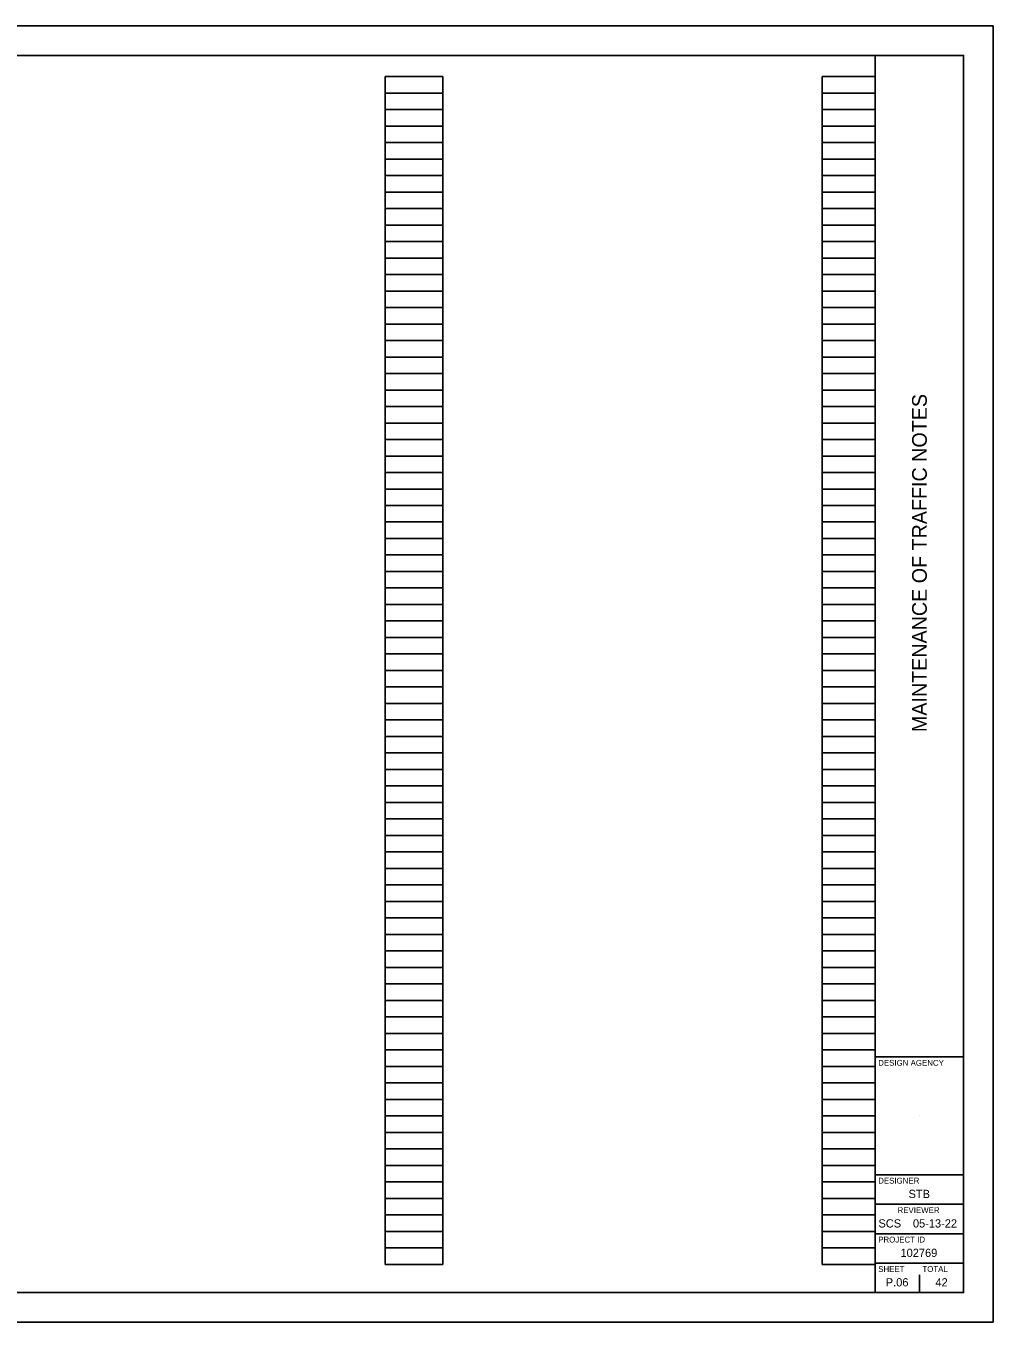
# Model space of a CAD drawing. Extents: x 0 to 34, y -1.2 to 22.
# Drawn here: x 17.58 to 34, y 0 to 22 of the extents above; entities that cross this region are included whole.
import ezdxf

# ---------------------------------------------------------------- set-up
doc = ezdxf.new("R2010")
doc.units = 0
for name, color, linetype in [('SH_Border', 7, 'Continuous'), ('SH_Cut_Line', 7, 'Continuous'), ('SH_Data', 7, 'Continuous')]:
    doc.layers.add(name, color=color, linetype=linetype)

msp = doc.modelspace()

# ---------------------------------------------------------------- linework, layer by layer
at = {"layer": 'SH_Border'}
for p, q in [((32, 0.5), (32, 21.5)), ((32, 4.5), (33.5, 4.5)), ((32, 2.5), (33.5, 2.5)), ((32, 2), (33.5, 2)), ((32, 1.5), (33.5, 1.5)), ((32, 1), (33.5, 1))]:
    msp.add_line(p, q, dxfattribs=at)
msp.add_lwpolyline([(1.5, 21.5), (33.5, 21.5), (33.5, 0.5), (1.5, 0.5)], close=True, dxfattribs=at)
at = {"layer": 'SH_Cut_Line'}
msp.add_lwpolyline([(0, 0), (34, 0), (34, 22), (0, 22)], close=True, dxfattribs=at)
at = {"layer": 'SH_Data'}
for p, q in [((23.68, 0.98), (23.68, 21.14)), ((23.68, 21.14), (24.66, 21.14)), ((24.66, 0.98), (24.66, 21.14)), ((31.1, 0.98), (31.1, 21.14)), ((31.1, 21.14), (32, 21.14)), ((32, 0.98), (32, 21.14)), ((23.68, 20.86), (24.66, 20.86)), ((31.1, 20.86), (32, 20.86)), ((23.68, 20.58), (24.66, 20.58)), ((31.1, 20.58), (32, 20.58)), ((23.68, 20.3), (24.66, 20.3)), ((31.1, 20.3), (32, 20.3)), ((23.68, 20.02), (24.66, 20.02)), ((31.1, 20.02), (32, 20.02)), ((23.68, 19.74), (24.66, 19.74)), ((31.1, 19.74), (32, 19.74)), ((23.68, 19.46), (24.66, 19.46)), ((31.1, 19.46), (32, 19.46)), ((23.68, 19.18), (24.66, 19.18)), ((31.1, 19.18), (32, 19.18)), ((23.68, 18.9), (24.66, 18.9)), ((31.1, 18.9), (32, 18.9)), ((23.68, 18.62), (24.66, 18.62)), ((31.1, 18.62), (32, 18.62)), ((23.68, 18.34), (24.66, 18.34)), ((31.1, 18.34), (32, 18.34)), ((23.68, 18.06), (24.66, 18.06)), ((31.1, 18.06), (32, 18.06)), ((23.68, 17.78), (24.66, 17.78)), ((31.1, 17.78), (32, 17.78)), ((23.68, 17.5), (24.66, 17.5)), ((31.1, 17.5), (32, 17.5)), ((23.68, 17.22), (24.66, 17.22)), ((31.1, 17.22), (32, 17.22)), ((23.68, 16.94), (24.66, 16.94)), ((31.1, 16.94), (32, 16.94)), ((23.68, 16.66), (24.66, 16.66)), ((31.1, 16.66), (32, 16.66)), ((23.68, 16.38), (24.66, 16.38)), ((31.1, 16.38), (32, 16.38)), ((23.68, 16.1), (24.66, 16.1)), ((31.1, 16.1), (32, 16.1)), ((23.68, 15.82), (24.66, 15.82)), ((31.1, 15.82), (32, 15.82)), ((23.68, 15.54), (24.66, 15.54)), ((31.1, 15.54), (32, 15.54)), ((23.68, 15.26), (24.66, 15.26)), ((31.1, 15.26), (32, 15.26)), ((23.68, 14.98), (24.66, 14.98)), ((31.1, 14.98), (32, 14.98)), ((23.68, 14.7), (24.66, 14.7)), ((31.1, 14.7), (32, 14.7)), ((23.68, 14.42), (24.66, 14.42)), ((31.1, 14.42), (32, 14.42)), ((23.68, 14.14), (24.66, 14.14)), ((31.1, 14.14), (32, 14.14)), ((23.68, 13.86), (24.66, 13.86)), ((31.1, 13.86), (32, 13.86)), ((23.68, 13.58), (24.66, 13.58)), ((31.1, 13.58), (32, 13.58)), ((23.68, 13.3), (24.66, 13.3)), ((31.1, 13.3), (32, 13.3)), ((23.68, 13.02), (24.66, 13.02)), ((31.1, 13.02), (32, 13.02)), ((23.68, 12.74), (24.66, 12.74)), ((31.1, 12.74), (32, 12.74)), ((23.68, 12.46), (24.66, 12.46)), ((31.1, 12.46), (32, 12.46)), ((23.68, 12.18), (24.66, 12.18)), ((31.1, 12.18), (32, 12.18)), ((23.68, 11.9), (24.66, 11.9)), ((31.1, 11.9), (32, 11.9)), ((23.68, 11.62), (24.66, 11.62)), ((31.1, 11.62), (32, 11.62)), ((23.68, 11.34), (24.66, 11.34)), ((31.1, 11.34), (32, 11.34)), ((23.68, 11.06), (24.66, 11.06)), ((31.1, 11.06), (32, 11.06)), ((23.68, 10.78), (24.66, 10.78)), ((31.1, 10.78), (32, 10.78)), ((23.68, 10.5), (24.66, 10.5)), ((31.1, 10.5), (32, 10.5)), ((23.68, 10.22), (24.66, 10.22)), ((31.1, 10.22), (32, 10.22)), ((23.68, 9.94), (24.66, 9.94)), ((31.1, 9.94), (32, 9.94)), ((23.68, 9.66), (24.66, 9.66)), ((31.1, 9.66), (32, 9.66)), ((23.68, 9.38), (24.66, 9.38)), ((31.1, 9.38), (32, 9.38)), ((23.68, 9.1), (24.66, 9.1)), ((31.1, 9.1), (32, 9.1)), ((23.68, 8.82), (24.66, 8.82)), ((31.1, 8.82), (32, 8.82)), ((23.68, 8.54), (24.66, 8.54)), ((31.1, 8.54), (32, 8.54)), ((23.68, 8.26), (24.66, 8.26)), ((31.1, 8.26), (32, 8.26)), ((23.68, 7.98), (24.66, 7.98)), ((31.1, 7.98), (32, 7.98)), ((23.68, 7.7), (24.66, 7.7)), ((31.1, 7.7), (32, 7.7)), ((23.68, 7.42), (24.66, 7.42)), ((31.1, 7.42), (32, 7.42)), ((23.68, 7.14), (24.66, 7.14)), ((31.1, 7.14), (32, 7.14)), ((23.68, 6.86), (24.66, 6.86)), ((31.1, 6.86), (32, 6.86)), ((23.68, 6.58), (24.66, 6.58)), ((31.1, 6.58), (32, 6.58)), ((23.68, 6.3), (24.66, 6.3)), ((31.1, 6.3), (32, 6.3)), ((23.68, 6.02), (24.66, 6.02)), ((31.1, 6.02), (32, 6.02)), ((23.68, 5.74), (24.66, 5.74)), ((31.1, 5.74), (32, 5.74)), ((23.68, 5.46), (24.66, 5.46)), ((31.1, 5.46), (32, 5.46)), ((23.68, 5.18), (24.66, 5.18)), ((31.1, 5.18), (32, 5.18)), ((23.68, 4.9), (24.66, 4.9)), ((31.1, 4.9), (32, 4.9)), ((23.68, 4.62), (24.66, 4.62)), ((31.1, 4.62), (32, 4.62)), ((23.68, 4.34), (24.66, 4.34)), ((31.1, 4.34), (32, 4.34)), ((23.68, 4.06), (24.66, 4.06)), ((31.1, 4.06), (32, 4.06)), ((23.68, 3.78), (24.66, 3.78)), ((31.1, 3.78), (32, 3.78)), ((23.68, 3.5), (24.66, 3.5)), ((31.1, 3.5), (32, 3.5)), ((32.75, 3.5), (32.75, 3.5)), ((23.68, 3.22), (24.66, 3.22)), ((31.1, 3.22), (32, 3.22)), ((23.68, 2.94), (24.66, 2.94)), ((31.1, 2.94), (32, 2.94)), ((23.68, 2.66), (24.66, 2.66)), ((31.1, 2.66), (32, 2.66)), ((23.68, 2.38), (24.66, 2.38)), ((31.1, 2.38), (32, 2.38)), ((23.68, 2.1), (24.66, 2.1)), ((31.1, 2.1), (32, 2.1)), ((23.68, 1.82), (24.66, 1.82)), ((31.1, 1.82), (32, 1.82)), ((23.68, 1.54), (24.66, 1.54)), ((31.1, 1.54), (32, 1.54)), ((23.68, 1.26), (24.66, 1.26)), ((31.1, 1.26), (32, 1.26)), ((23.68, 0.98), (24.66, 0.98)), ((31.1, 0.98), (32, 0.98)), ((32.375, 0.675), (32.375, 0.675)), ((32.75, 0.5), (32.75, 0.8))]:
    msp.add_line(p, q, dxfattribs=at)

# ---------------------------------------------------------------- texts
msp.add_text('MAINTENANCE OF TRAFFIC NOTES', height=0.25, rotation=90, dxfattribs=at).set_placement((32.875, 10.014))
for s, height, p in [('DESIGN AGENCY', 0.1, (32.05, 4.35)), ('DESIGNER', 0.1, (32.05, 2.35)), ('STB', 0.14, (32.565, 2.105)), ('REVIEWER', 0.1, (32.378, 1.85)), ('SCS', 0.14, (32.054, 1.605)), ('05-13-22', 0.14, (32.639, 1.605)), ('PROJECT ID', 0.1, (32.05, 1.35)), ('102769', 0.14, (32.428, 1.105)), ('SHEET', 0.1, (32.05, 0.85)), ('TOTAL', 0.1, (32.8, 0.85)), ('P.06', 0.14, (32.178, 0.605)), ('42', 0.14, (33.021, 0.605))]:
    msp.add_text(s, height=height, dxfattribs=at).set_placement(p)

doc.saveas('drawing.dxf')
